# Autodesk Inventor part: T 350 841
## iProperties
Company: Mayer & Müller AG Schaltgeräte
Created: 2006-10
Part Number: T 350 841
Material: 2.0060.30
Document SubType Name: Modeling
Designer: I.Baliuc
Manufacturer: Standard
Standards Organization: Custom
Description: Vorkontaktsockel
Density: 8.94 g/cm^3
Author: T.Messerschmitt
Revision Number: 350841
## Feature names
1. Extrusion2
2. Extrusion3
3. Bohrung_M6 [Hole]
4. Extrusion5
